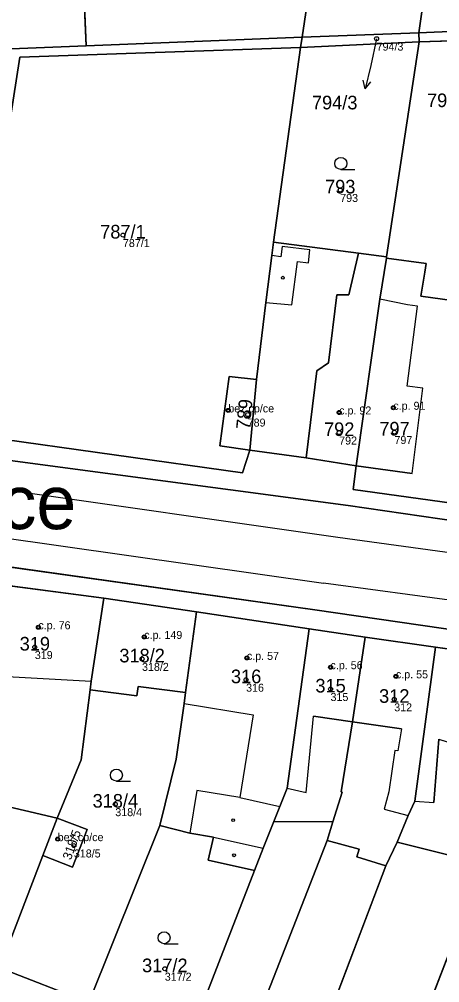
# Model space of a CAD drawing. Extents: x -603967 to -594699, y -1179315 to -1165625.
# Drawn here: x -597834.2 to -597781.7, y -1172370 to -1172249.7 of the extents above; entities that cross this region are included whole.
import ezdxf

# ---------------------------------------------------------------- set-up
doc = ezdxf.new("R2010")
doc.units = 0
for name, color, linetype in [('Definiční body', 7, 'Continuous'), ('Hranice parcel', 7, 'Continuous'), ('Parcelní čísla', 7, 'Continuous'), ('Polygon budovy', 7, 'Continuous'), ('Polygon parcely', 7, 'Continuous'), ('Pop  PČ popisy', 7, 'Continuous'), ('Vnitřní kresba', 7, 'Continuous'), ('Značky budov', 7, 'Continuous'), ('Značky kultur', 7, 'Continuous')]:
    doc.layers.add(name, color=color, linetype=linetype)

msp = doc.modelspace()

# ---------------------------------------------------------------- linework, layer by layer
at = {"layer": 'Definiční body'}
for centre in [(-597789.57, -1172252.14994), (-597794.12, -1172271.04994), (-597821.27, -1172276.67994), (-597808.1, -1172298.56994), (-597794.25, -1172298.82994), (-597787.48, -1172298.23994), (-597805.68, -1172299.09994), (-597794.25, -1172301.33994), (-597787.34, -1172301.27994), (-597831.83, -1172325.64994), (-597818.61, -1172326.85994), (-597832.28, -1172328.12994), (-597818.88, -1172329.60994), (-597805.78, -1172329.47994), (-597795.33, -1172330.63994), (-597805.88, -1172332.20994), (-597787.16, -1172331.77994), (-597795.33, -1172333.36994), (-597787.37, -1172334.65994), (-597822.22, -1172347.74994), (-597829.42, -1172352.10994), (-597827.4, -1172352.90994), (-597816.04, -1172368.29994)]:
    msp.add_circle(centre, 0.25, dxfattribs=at)
at = {"layer": 'Hranice parcel'}
for p, q in [((-597829.48, -1172170.13), (-597825.85, -1172253.05)), ((-597798.87, -1172251.98), (-597797.31, -1172241.32)), ((-597783.07, -1172242.87), (-597784.29, -1172251.4)), ((-597784.29, -1172251.4), (-597798.87, -1172251.98)), ((-597784.29, -1172251.4), (-597779.47, -1172251.21)), ((-597784.27, -1172252.55), (-597784.29, -1172251.4)), ((-597825.85, -1172253.05), (-597798.87, -1172251.98)), ((-597798.87, -1172251.98), (-597799.1, -1172253.23)), ((-597799.1, -1172253.23), (-597784.27, -1172252.55)), ((-597784.27, -1172252.55), (-597788.32, -1172279.39)), ((-597770.29, -1172252.12), (-597784.27, -1172252.55)), ((-597836.28, -1172253.46), (-597825.85, -1172253.05)), ((-597802.47, -1172277.54), (-597799.1, -1172253.23)), ((-597788.34, -1172279.54), (-597788.32, -1172279.39)), ((-597804.59, -1172294.69), (-597808, -1172294.35)), ((-597805.42, -1172303.54), (-597804.59, -1172294.69)), ((-597797.27, -1172323.47), (-597956.98, -1172301.12)), ((-597823.64, -1172322), (-597837.68, -1172320.18)), ((-597823.64, -1172322), (-597812.09, -1172323.71)), ((-597812.09, -1172323.71), (-597813.43, -1172333.81)), ((-597798.01, -1172325.85), (-597812.09, -1172323.71)), ((-597798.01, -1172325.85), (-597791.02, -1172326.88)), ((-597782.22, -1172328.12), (-597791.02, -1172326.88)), ((-597782.22, -1172328.12), (-597784.8, -1172347.36)), ((-597771.48, -1172329.67), (-597782.22, -1172328.12)), ((-597813.43, -1172333.81), (-597813.61, -1172335.18)), ((-597829.49, -1172349.49), (-597831.29, -1172354.15)), ((-597825.53, -1172372.51), (-597816.66, -1172350.41)), ((-597816.66, -1172350.41), (-597812.91, -1172351.35)), ((-597795.04, -1172349.96), (-597802.42, -1172349.89)), ((-597795.04, -1172349.96), (-597795.76, -1172352.27)), ((-597795.76, -1172352.27), (-597826.82, -1172431.75)), ((-597787.02, -1172352.5), (-597788.42, -1172355.44)), ((-597831.29, -1172354.15), (-597836.71, -1172368.19)), ((-597817.42, -1172388.45), (-597804.84, -1172356.04)), ((-597788.42, -1172355.44), (-597803.75, -1172395.8)), ((-597778.48, -1172361.01), (-597796.02, -1172406.49)), ((-597825.53, -1172372.51), (-597836.71, -1172368.19))]:
    msp.add_line(p, q, dxfattribs=at)
for points in [[(-597799.1, -1172253.23), (-597834.14, -1172254.47), (-597841.01, -1172298.48)], [(-597802.47, -1172277.54), (-597802.68, -1172279.24), (-597803.4, -1172285.08), (-597804.59, -1172294.69)], [(-597788.32, -1172279.39), (-597791.82, -1172278.93), (-597802.47, -1172277.54)], [(-597792.13, -1172305.48), (-597789.15, -1172284.66), (-597788.34, -1172279.54)], [(-597788.34, -1172279.54), (-597783.36, -1172280.24), (-597783.54, -1172281.3)], [(-597783.54, -1172281.3), (-597784.05, -1172284.31), (-597778.64, -1172285.07), (-597775.06, -1172285.57)], [(-597808, -1172294.35), (-597809.17, -1172302.98), (-597805.42, -1172303.54)], [(-597838.43, -1172301.85), (-597806.33, -1172306.37), (-597805.42, -1172303.54)], [(-597731.68, -1172318.8), (-597765.64, -1172314.46), (-597793.13, -1172310.44), (-597851.99, -1172302.61)], [(-597805.42, -1172303.54), (-597798.38, -1172304.5), (-597792.13, -1172305.48)], [(-597792.13, -1172305.48), (-597792.5, -1172308.44), (-597778.67, -1172310.35), (-597778.18, -1172307.46)], [(-597825.36, -1172333.47), (-597825.22, -1172332.4), (-597823.64, -1172322)], [(-597737.75, -1172331.93), (-597770.58, -1172327.35), (-597797.27, -1172323.47)], [(-597802.42, -1172349.89), (-597801.67, -1172348.02), (-597800.75, -1172345.73), (-597798.01, -1172325.85)], [(-597791.02, -1172326.88), (-597792.6, -1172337.47), (-597794.01, -1172346.2), (-597793.88, -1172346.24), (-597795.04, -1172349.96)], [(-597825.36, -1172333.47), (-597826.48, -1172342.22), (-597829.49, -1172349.49)], [(-597813.43, -1172333.81), (-597819.36, -1172333.05), (-597819.51, -1172334.22), (-597825.36, -1172333.47)], [(-597813.61, -1172335.18), (-597814.62, -1172342.11), (-597816.66, -1172350.41)], [(-597842.99, -1172346.35), (-597837.67, -1172347.59), (-597829.49, -1172349.49)], [(-597784.8, -1172347.36), (-597785.63, -1172349.15), (-597787.02, -1172352.5)], [(-597829.49, -1172349.49), (-597825.75, -1172350.91), (-597827.56, -1172355.59), (-597831.29, -1172354.15)], [(-597804.84, -1172356.04), (-597803.76, -1172353.24), (-597802.42, -1172349.89)], [(-597812.91, -1172351.35), (-597809.94, -1172351.85), (-597810.6, -1172354.73), (-597804.84, -1172356.04)], [(-597795.76, -1172352.27), (-597791.74, -1172353.36), (-597792.03, -1172354.31), (-597788.42, -1172355.44)], [(-597776.25, -1172355.24), (-597780.33, -1172354.14), (-597787.02, -1172352.5)]]:
    msp.add_lwpolyline(points, dxfattribs=at)
at = {"layer": 'Polygon budovy'}
for points in [[(-597798.38, -1172304.5), (-597792.13, -1172305.48), (-597789.15, -1172284.66), (-597788.34, -1172279.54), (-597788.32, -1172279.39), (-597791.82, -1172278.93), (-597793.05, -1172284.12), (-597794.55, -1172284.12), (-597795.57, -1172292.64), (-597797.06, -1172293.62)], [(-597789.15, -1172284.66), (-597792.13, -1172305.48), (-597785.11, -1172306.44), (-597783.79, -1172295.8), (-597785.74, -1172295.55), (-597784.46, -1172285.54), (-597785.72, -1172285.38)], [(-597809.17, -1172302.98), (-597805.42, -1172303.54), (-597804.59, -1172294.69), (-597808, -1172294.35)], [(-597840.24, -1172339.2), (-597842.99, -1172346.35), (-597837.67, -1172347.59), (-597835.73, -1172331.81), (-597825.22, -1172332.4), (-597823.64, -1172322), (-597837.68, -1172320.18)], [(-597819.36, -1172333.05), (-597813.43, -1172333.81), (-597812.09, -1172323.71), (-597823.64, -1172322), (-597825.22, -1172332.4), (-597825.36, -1172333.47), (-597819.51, -1172334.22)], [(-597813.61, -1172335.18), (-597804.98, -1172336.57), (-597806.64, -1172346.89), (-597801.67, -1172348.02), (-597800.75, -1172345.73), (-597798.01, -1172325.85), (-597812.09, -1172323.71), (-597813.43, -1172333.81)], [(-597798.01, -1172325.85), (-597800.75, -1172345.73), (-597798.36, -1172346.28), (-597797.47, -1172336.77), (-597792.6, -1172337.47), (-597791.02, -1172326.88)], [(-597782.22, -1172328.12), (-597791.02, -1172326.88), (-597792.6, -1172337.47), (-597786.46, -1172338.35), (-597786.9, -1172341.09), (-597787.28, -1172341.03), (-597788.04, -1172346.2), (-597788.61, -1172348.37), (-597785.63, -1172349.15), (-597784.8, -1172347.36)], [(-597771.48, -1172329.67), (-597782.22, -1172328.12), (-597784.8, -1172347.36), (-597782.4, -1172347.55), (-597781.78, -1172339.62), (-597776.08, -1172341.44), (-597776.99, -1172349.62), (-597774.33, -1172350.05)], [(-597829.49, -1172349.49), (-597831.29, -1172354.15), (-597827.56, -1172355.59), (-597825.75, -1172350.91)]]:
    msp.add_lwpolyline(points, close=True, dxfattribs=at)
at = {"layer": 'Polygon parcely'}
for points in [[(-597834.36, -1172239.94), (-597836.28, -1172253.46), (-597825.85, -1172253.05), (-597829.48, -1172170.13), (-597833.06, -1172088.34), (-597831.1, -1172058.3), (-597847.92, -1172055.46), (-597847.61, -1172059.45), (-597845.34, -1172059.79), (-597847.18, -1172071.71), (-597846.59, -1172089.99), (-597845.84, -1172113.39), (-597845.11, -1172136.22), (-597844.61, -1172151.68), (-597844.14, -1172166.41), (-597843.64, -1172182.07), (-597843.13, -1172197.94), (-597842.67, -1172212.45), (-597842.35, -1172222.49), (-597842.32, -1172223.4), (-597838.6, -1172224.04), (-597837.46, -1172226.22), (-597839.15, -1172239.19)], [(-597829.48, -1172170.13), (-597825.85, -1172253.05), (-597798.87, -1172251.98), (-597797.31, -1172241.32), (-597796.08, -1172231.92), (-597789.45, -1172188.6), (-597789.15, -1172186.55), (-597784.85, -1172187.33), (-597782.78, -1172168.28)], [(-597784.29, -1172251.4), (-597779.47, -1172251.21), (-597780.36, -1172223.97), (-597783.07, -1172242.87)], [(-597797.31, -1172241.32), (-597798.87, -1172251.98), (-597784.29, -1172251.4), (-597783.07, -1172242.87)], [(-597784.27, -1172252.55), (-597784.29, -1172251.4), (-597798.87, -1172251.98), (-597799.1, -1172253.23)], [(-597770.29, -1172252.12), (-597769.97, -1172250.95), (-597779.47, -1172251.21), (-597784.29, -1172251.4), (-597784.27, -1172252.55)], [(-597846.51, -1172291.29), (-597841.01, -1172298.48), (-597834.14, -1172254.47), (-597799.1, -1172253.23), (-597798.87, -1172251.98), (-597825.85, -1172253.05), (-597836.28, -1172253.46), (-597841.25, -1172253.65), (-597841.48, -1172255.09), (-597837.95, -1172255.68), (-597839.74, -1172268.6), (-597843.27, -1172268), (-597846.43, -1172290.68)], [(-597802.47, -1172277.54), (-597791.82, -1172278.93), (-597788.32, -1172279.39), (-597784.27, -1172252.55), (-597799.1, -1172253.23)], [(-597783.36, -1172280.24), (-597783.54, -1172281.3), (-597784.05, -1172284.31), (-597778.64, -1172285.07), (-597775.06, -1172285.57), (-597770.29, -1172252.12), (-597784.27, -1172252.55), (-597788.32, -1172279.39), (-597788.34, -1172279.54)], [(-597805.42, -1172303.54), (-597809.17, -1172302.98), (-597808, -1172294.35), (-597804.59, -1172294.69), (-597803.4, -1172285.08), (-597802.68, -1172279.24), (-597802.47, -1172277.54), (-597799.1, -1172253.23), (-597834.14, -1172254.47), (-597841.01, -1172298.48), (-597838.43, -1172301.85), (-597806.33, -1172306.37)], [(-597804.59, -1172294.69), (-597805.42, -1172303.54), (-597798.38, -1172304.5), (-597792.13, -1172305.48), (-597789.15, -1172284.66), (-597788.34, -1172279.54), (-597788.32, -1172279.39), (-597791.82, -1172278.93), (-597802.47, -1172277.54), (-597802.68, -1172279.24), (-597803.4, -1172285.08)], [(-597778.67, -1172310.35), (-597778.18, -1172307.46), (-597776.74, -1172297.27), (-597775.06, -1172285.57), (-597778.64, -1172285.07), (-597784.05, -1172284.31), (-597783.54, -1172281.3), (-597783.36, -1172280.24), (-597788.34, -1172279.54), (-597789.15, -1172284.66), (-597792.13, -1172305.48), (-597792.5, -1172308.44)], [(-597804.59, -1172294.69), (-597808, -1172294.35), (-597809.17, -1172302.98), (-597805.42, -1172303.54)], [(-597837.67, -1172347.59), (-597829.49, -1172349.49), (-597826.48, -1172342.22), (-597825.36, -1172333.47), (-597825.22, -1172332.4), (-597823.64, -1172322), (-597837.68, -1172320.18), (-597840.24, -1172339.2), (-597842.99, -1172346.35)], [(-597813.43, -1172333.81), (-597812.09, -1172323.71), (-597823.64, -1172322), (-597825.22, -1172332.4), (-597825.36, -1172333.47), (-597819.51, -1172334.22), (-597819.36, -1172333.05)], [(-597812.91, -1172351.35), (-597809.94, -1172351.85), (-597810.6, -1172354.73), (-597804.84, -1172356.04), (-597803.76, -1172353.24), (-597802.42, -1172349.89), (-597801.67, -1172348.02), (-597800.75, -1172345.73), (-597798.01, -1172325.85), (-597812.09, -1172323.71), (-597813.43, -1172333.81), (-597813.61, -1172335.18), (-597814.62, -1172342.11), (-597816.66, -1172350.41)], [(-597795.04, -1172349.96), (-597793.88, -1172346.24), (-597794.01, -1172346.2), (-597792.6, -1172337.47), (-597791.02, -1172326.88), (-597798.01, -1172325.85), (-597800.75, -1172345.73), (-597801.67, -1172348.02), (-597802.42, -1172349.89)], [(-597788.42, -1172355.44), (-597787.02, -1172352.5), (-597785.63, -1172349.15), (-597784.8, -1172347.36), (-597782.22, -1172328.12), (-597791.02, -1172326.88), (-597792.6, -1172337.47), (-597794.01, -1172346.2), (-597793.88, -1172346.24), (-597795.04, -1172349.96), (-597795.76, -1172352.27), (-597791.74, -1172353.36), (-597792.03, -1172354.31)], [(-597782.22, -1172328.12), (-597784.8, -1172347.36), (-597785.63, -1172349.15), (-597787.02, -1172352.5), (-597780.33, -1172354.14), (-597776.25, -1172355.24), (-597775.47, -1172353.21), (-597775.28, -1172352.71), (-597774.47, -1172350.77), (-597774.33, -1172350.05), (-597771.48, -1172329.67)], [(-597826.48, -1172342.22), (-597829.49, -1172349.49), (-597825.75, -1172350.91), (-597827.56, -1172355.59), (-597831.29, -1172354.15), (-597836.71, -1172368.19), (-597825.53, -1172372.51), (-597816.66, -1172350.41), (-597814.62, -1172342.11), (-597813.61, -1172335.18), (-597813.43, -1172333.81), (-597819.36, -1172333.05), (-597819.51, -1172334.22), (-597825.36, -1172333.47)], [(-597850.14, -1172364.92), (-597852.42, -1172370.84), (-597839.64, -1172375.77), (-597836.71, -1172368.19), (-597831.29, -1172354.15), (-597829.49, -1172349.49), (-597837.67, -1172347.59), (-597842.99, -1172346.35), (-597843.28, -1172347.1)], [(-597795.04, -1172349.96), (-597802.42, -1172349.89), (-597803.76, -1172353.24), (-597804.84, -1172356.04), (-597817.42, -1172388.45), (-597833.38, -1172429.92), (-597826.82, -1172431.75), (-597795.76, -1172352.27)], [(-597831.29, -1172354.15), (-597827.56, -1172355.59), (-597825.75, -1172350.91), (-597829.49, -1172349.49)], [(-597817.42, -1172388.45), (-597804.84, -1172356.04), (-597810.6, -1172354.73), (-597809.94, -1172351.85), (-597812.91, -1172351.35), (-597816.66, -1172350.41), (-597825.53, -1172372.51), (-597829.85, -1172383.66)], [(-597816.08, -1172428.24), (-597803.75, -1172395.8), (-597788.42, -1172355.44), (-597792.03, -1172354.31), (-597791.74, -1172353.36), (-597795.76, -1172352.27), (-597826.82, -1172431.75), (-597820.81, -1172433.27), (-597819.59, -1172427.5), (-597816.6, -1172428.13)], [(-597801.67, -1172404.22), (-597796.02, -1172406.49), (-597778.48, -1172361.01), (-597777.45, -1172358.34), (-597776.25, -1172355.24), (-597780.33, -1172354.14), (-597787.02, -1172352.5), (-597788.42, -1172355.44), (-597803.75, -1172395.8), (-597799.04, -1172397.63)], [(-597796.02, -1172406.49), (-597807.31, -1172435.77), (-597801.55, -1172437.37), (-597772.73, -1172362.82), (-597778.48, -1172361.01)], [(-597844.6, -1172420.9), (-597838.33, -1172405.07), (-597829.85, -1172383.66), (-597825.53, -1172372.51), (-597836.71, -1172368.19), (-597839.64, -1172375.77), (-597858.22, -1172423.91), (-597846.88, -1172426.7), (-597850.47, -1172425.33), (-597848.31, -1172419.68), (-597844.67, -1172421.08)]]:
    msp.add_lwpolyline(points, close=True, dxfattribs=at)
for points in [[(-597534.75, -1172348.6), (-597559.28, -1172345.76), (-597603.32, -1172338.5), (-597661.75, -1172328.26), (-597662.94, -1172328.05), (-597706, -1172323.18), (-597731.68, -1172318.8), (-597765.64, -1172314.46), (-597793.13, -1172310.44), (-597851.99, -1172302.61), (-597960.77, -1172287.58), (-597964.7, -1172286.91), (-597986.41, -1172283.87), (-598031.69, -1172277.53)], [(-598037.57, -1172289.67), (-597969.21, -1172299.41), (-597966.22, -1172299.84), (-597956.98, -1172301.12), (-597797.27, -1172323.47), (-597770.58, -1172327.35), (-597737.75, -1172331.93), (-597704.89, -1172336.54), (-597674.14, -1172341.49), (-597673.16, -1172341.62), (-597665.62, -1172342.61), (-597661.18, -1172343.19), (-597660.8, -1172342.11), (-597591.42, -1172351.56), (-597523.81, -1172359.42)], [(-597674.14, -1172341.49), (-597704.89, -1172336.54), (-597737.75, -1172331.93), (-597770.58, -1172327.35), (-597797.27, -1172323.47), (-597956.98, -1172301.12)], [(-597691.27, -1172322.46), (-597706.22, -1172320.56), (-597722.83, -1172318.11), (-597730.82, -1172316.93), (-597730.48, -1172314.13), (-597734.41, -1172313.54), (-597742.28, -1172312.49), (-597742.49, -1172315.48), (-597750.76, -1172314.31), (-597757.82, -1172313.33), (-597764.82, -1172312.34), (-597764.56, -1172309.28), (-597775.2, -1172307.87), (-597778.18, -1172307.46), (-597778.67, -1172310.35), (-597792.5, -1172308.44), (-597792.13, -1172305.48), (-597798.38, -1172304.5), (-597805.42, -1172303.54), (-597806.33, -1172306.37), (-597838.43, -1172301.85)], [(-597851.99, -1172302.61), (-597793.13, -1172310.44), (-597765.64, -1172314.46), (-597731.68, -1172318.8), (-597706, -1172323.18), (-597662.94, -1172328.05)], [(-597837.68, -1172320.18), (-597823.64, -1172322), (-597812.09, -1172323.71), (-597798.01, -1172325.85), (-597791.02, -1172326.88), (-597782.22, -1172328.12), (-597771.48, -1172329.67), (-597765.4, -1172330.46), (-597759.38, -1172331.34), (-597752.44, -1172332.27), (-597745.71, -1172333.23), (-597738.8, -1172334.2), (-597731.86, -1172335.26), (-597721.89, -1172336.59), (-597711.75, -1172337.91), (-597704.68, -1172338.99), (-597691.02, -1172340.89)]]:
    msp.add_lwpolyline(points, dxfattribs=at)
at = {"layer": 'Pop  PČ popisy'}
for p, q in [((-597789.57, -1172252.15), (-597790.31, -1172255.48)), ((-597790.31, -1172255.48), (-597790.985, -1172258.404)), ((-597790.985, -1172258.404), (-597791.248, -1172257.316)), ((-597790.985, -1172258.404), (-597790.272, -1172257.541))]:
    msp.add_line(p, q, dxfattribs=at)
at = {"layer": 'Vnitřní kresba'}
for p, q in [((-597801.38, -1172278.11), (-597801.53, -1172279.4)), ((-597797.91, -1172278.5), (-597801.38, -1172278.11)), ((-597801.53, -1172279.4), (-597802.68, -1172279.24)), ((-597798.08, -1172280.12), (-597797.91, -1172278.5)), ((-597793.05, -1172284.12), (-597791.82, -1172278.93)), ((-597794.4, -1172314.43), (-598033.11, -1172280.47)), ((-597800.17, -1172285.39), (-597799.44, -1172279.97)), ((-597799.44, -1172279.97), (-597798.08, -1172280.12)), ((-597795.57, -1172292.64), (-597794.55, -1172284.12)), ((-597794.55, -1172284.12), (-597793.05, -1172284.12)), ((-597803.4, -1172285.08), (-597800.17, -1172285.39)), ((-597785.72, -1172285.38), (-597789.15, -1172284.66)), ((-597784.46, -1172285.54), (-597785.72, -1172285.38)), ((-597785.74, -1172295.55), (-597784.46, -1172285.54)), ((-597797.06, -1172293.62), (-597795.57, -1172292.64)), ((-597798.38, -1172304.5), (-597797.06, -1172293.62)), ((-597967.08, -1172295.87), (-597796.21, -1172320.14)), ((-597783.79, -1172295.8), (-597785.74, -1172295.55)), ((-597785.11, -1172306.44), (-597783.79, -1172295.8)), ((-597785.11, -1172306.44), (-597792.13, -1172305.48)), ((-597767.07, -1172318.19), (-597794.4, -1172314.43)), ((-597769.23, -1172323.8), (-597796.21, -1172320.14)), ((-597835.73, -1172331.81), (-597825.22, -1172332.4)), ((-597813.61, -1172335.18), (-597804.98, -1172336.57)), ((-597804.98, -1172336.57), (-597806.64, -1172346.89)), ((-597798.36, -1172346.28), (-597797.47, -1172336.77)), ((-597792.6, -1172337.47), (-597797.47, -1172336.77)), ((-597786.46, -1172338.35), (-597792.6, -1172337.47)), ((-597786.46, -1172338.35), (-597786.9, -1172341.09)), ((-597781.78, -1172339.62), (-597782.4, -1172347.55)), ((-597781.78, -1172339.62), (-597776.08, -1172341.44)), ((-597787.28, -1172341.03), (-597788.04, -1172346.2)), ((-597786.9, -1172341.09), (-597787.28, -1172341.03)), ((-597812.04, -1172346.02), (-597812.91, -1172351.35)), ((-597806.64, -1172346.89), (-597812.04, -1172346.02)), ((-597800.75, -1172345.73), (-597798.36, -1172346.28)), ((-597788.04, -1172346.2), (-597788.61, -1172348.37)), ((-597806.64, -1172346.89), (-597801.67, -1172348.02)), ((-597784.8, -1172347.36), (-597782.4, -1172347.55)), ((-597788.61, -1172348.37), (-597785.63, -1172349.15)), ((-597809.94, -1172351.85), (-597803.76, -1172353.24))]:
    msp.add_line(p, q, dxfattribs=at)
at = {"layer": 'Značky budov'}
for centre in [(-597801.2968, -1172281.99916), (-597808.1068, -1172298.56916), (-597794.2568, -1172298.82916), (-597787.4868, -1172298.23916), (-597831.8368, -1172325.64916), (-597818.6168, -1172326.85916), (-597805.7868, -1172329.47916), (-597795.3368, -1172330.63916), (-597787.1668, -1172331.77916), (-597807.4968, -1172349.74916), (-597829.4268, -1172352.10916), (-597807.3868, -1172354.12916)]:
    msp.add_circle(centre, 0.175, dxfattribs=at)
at = {"layer": 'Značky kultur'}
for p, q in [((-597794.043, -1172268.48), (-597792.293, -1172268.48)), ((-597822.083, -1172344.86), (-597820.333, -1172344.86)), ((-597816.133, -1172365.17), (-597814.383, -1172365.17))]:
    msp.add_line(p, q, dxfattribs=at)
for centre in [(-597794.04286, -1172267.72981), (-597822.08286, -1172344.10981), (-597816.13286, -1172364.41981)]:
    msp.add_circle(centre, 0.75, dxfattribs=at)

# ---------------------------------------------------------------- texts
at = {"layer": 'Definiční body'}
for s, p in [('794/3', (-597789.57, -1172253.639)), ('793', (-597794.12, -1172272.539)), ('787/1', (-597821.27, -1172278.169)), ('c.p. 91', (-597787.48, -1172298.49)), ('bez cp/ce', (-597808.1, -1172298.82)), ('c.p. 92', (-597794.25, -1172299.08)), ('789', (-597805.68, -1172300.589)), ('792', (-597794.25, -1172302.829)), ('797', (-597787.34, -1172302.769)), ('c.p. 76', (-597831.83, -1172325.9)), ('c.p. 149', (-597818.61, -1172327.11)), ('319', (-597832.28, -1172329.619)), ('c.p. 57', (-597805.78, -1172329.73)), ('c.p. 56', (-597795.33, -1172330.89)), ('318/2', (-597818.88, -1172331.099)), ('c.p. 55', (-597787.16, -1172332.03)), ('316', (-597805.88, -1172333.699)), ('315', (-597795.33, -1172334.859)), ('312', (-597787.37, -1172336.149)), ('318/4', (-597822.22, -1172349.239)), ('bez cp/ce', (-597829.42, -1172352.36)), ('318/5', (-597827.4, -1172354.399)), ('317/2', (-597816.04, -1172369.789))]:
    msp.add_text(s, height=0.999996, dxfattribs=at).set_placement(p)
at = {"layer": 'Parcelní čísla'}
for s, p in [('795/3', (-597783.272, -1172260.695)), ('794/3', (-597797.652, -1172260.975)), ('793', (-597796.01, -1172271.475)), ('787/1', (-597824.106, -1172277.105)), ('792', (-597796.14, -1172301.765)), ('797', (-597789.23, -1172301.705)), ('319', (-597834.17, -1172328.555)), ('318/2', (-597821.716, -1172330.035)), ('316', (-597807.77, -1172332.635)), ('315', (-597797.22, -1172333.795)), ('312', (-597789.26, -1172335.085)), ('318/4', (-597825.056, -1172348.175)), ('317/2', (-597818.876, -1172368.725))]:
    msp.add_text(s, height=1.699998, dxfattribs=at).set_placement(p)
for s, height, rotation, p in [('789', 1.699998, 84, (-597805.454, -1172301.024)), ('318/5', 1.14, 70, (-597827.782, -1172354.794))]:
    msp.add_text(s, height=height, rotation=rotation, dxfattribs=at).set_placement(p)
at = {"layer": 'Pop  PČ popisy'}
msp.add_text('Rajhradice', height=6.699996, dxfattribs=at).set_placement((-597869.924, -1172313.395))

doc.saveas('drawing.dxf')
